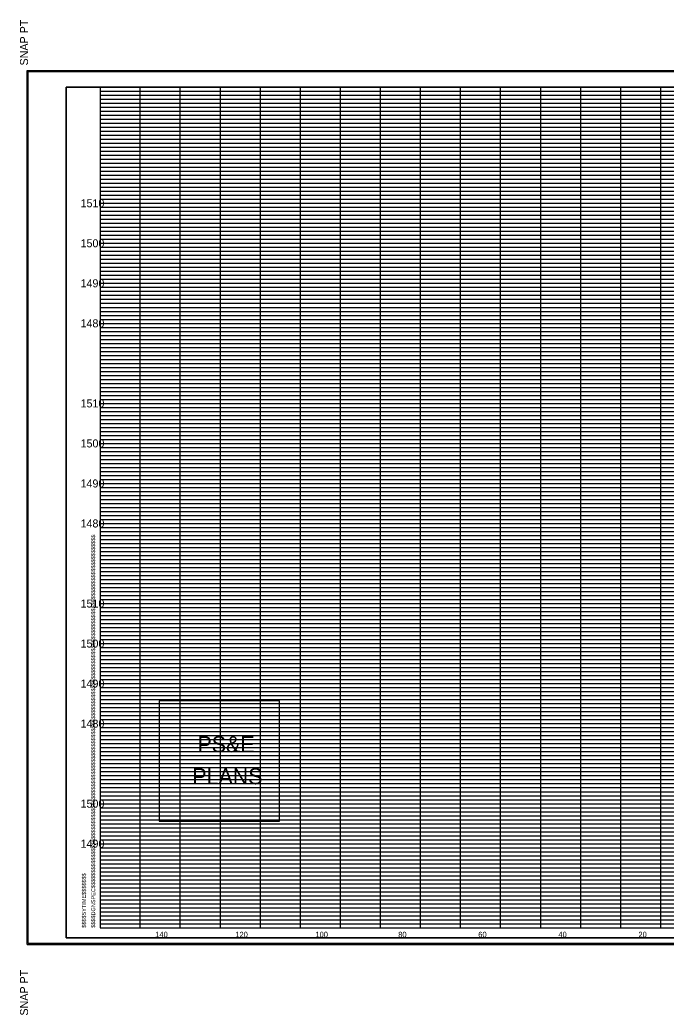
# Model space of a CAD drawing. Extents: x 980 to 1324, y 978 to 1497.
# Drawn here: x 979.9 to 1141.3, y 978.2 to 1226.8 of the extents above; entities that cross this region are included whole.
import ezdxf

# ---------------------------------------------------------------- set-up
doc = ezdxf.new("R2010")
doc.units = 0
for name, color, linetype in [('DESIGN - SHEET - Corner Text', 7, 'Continuous'), ('DESIGN - SHEET - Light Grid', 7, 'Continuous'), ('DESIGN - SHEET - Linework', 7, 'Continuous'), ('DESIGN - SHEET - Plot Shape', 7, 'Continuous'), ('DESIGN - TYPICAL - Text', 7, 'Continuous')]:
    doc.layers.add(name, color=color, linetype=linetype)

# ---------------------------------------------------------------- blocks, each defined once
blk = doc.blocks.new('XSTSHT')
at = {"layer": 'DESIGN - SHEET - Light Grid'}
for p, q in [((0, 20.9), (8, 20.9)), ((8, 20.9), (16, 20.9)), ((0, 20.8), (8, 20.8)), ((0, 20.7), (8, 20.7)), ((8, 20.8), (16, 20.8)), ((8, 20.7), (16, 20.7)), ((0, 20.6), (8, 20.6)), ((0, 20.5), (8, 20.5)), ((0, 20.4), (8, 20.4)), ((8, 20.6), (16, 20.6)), ((8, 20.5), (16, 20.5)), ((8, 20.4), (16, 20.4)), ((0, 20.3), (8, 20.3)), ((0, 20.2), (8, 20.2)), ((8, 20.3), (16, 20.3)), ((8, 20.2), (16, 20.2)), ((0, 20.1), (8, 20.1)), ((0, 19.9), (8, 19.9)), ((8, 20.1), (16, 20.1)), ((8, 19.9), (16, 19.9)), ((0, 19.8), (8, 19.8)), ((0, 19.7), (8, 19.7)), ((8, 19.8), (16, 19.8)), ((8, 19.7), (16, 19.7)), ((0, 19.6), (8, 19.6)), ((0, 19.5), (8, 19.5)), ((0, 19.4), (8, 19.4)), ((8, 19.6), (16, 19.6)), ((8, 19.5), (16, 19.5)), ((8, 19.4), (16, 19.4)), ((0, 19.3), (8, 19.3)), ((0, 19.2), (8, 19.2)), ((8, 19.3), (16, 19.3)), ((8, 19.2), (16, 19.2)), ((0, 19.1), (8, 19.1)), ((0, 18.9), (8, 18.9)), ((8, 19.1), (16, 19.1)), ((8, 18.9), (16, 18.9)), ((0, 18.8), (8, 18.8)), ((0, 18.7), (8, 18.7)), ((8, 18.8), (16, 18.8)), ((8, 18.7), (16, 18.7)), ((0, 18.6), (8, 18.6)), ((0, 18.5), (8, 18.5)), ((0, 18.4), (8, 18.4)), ((8, 18.6), (16, 18.6)), ((8, 18.5), (16, 18.5)), ((8, 18.4), (16, 18.4)), ((0, 18.3), (8, 18.3)), ((0, 18.2), (8, 18.2)), ((8, 18.3), (16, 18.3)), ((8, 18.2), (16, 18.2)), ((0, 18.1), (8, 18.1)), ((8, 18.1), (16, 18.1)), ((0, 17.9), (8, 17.9)), ((0, 17.8), (8, 17.8)), ((0, 17.7), (8, 17.7)), ((8, 17.9), (16, 17.9)), ((8, 17.8), (16, 17.8)), ((8, 17.7), (16, 17.7)), ((0, 17.6), (8, 17.6)), ((0, 17.5), (8, 17.5)), ((8, 17.6), (16, 17.6)), ((8, 17.5), (16, 17.5)), ((0, 17.4), (8, 17.4)), ((0, 17.3), (8, 17.3)), ((0, 17.2), (8, 17.2)), ((8, 17.4), (16, 17.4)), ((8, 17.3), (16, 17.3)), ((8, 17.2), (16, 17.2)), ((0, 17.1), (8, 17.1)), ((8, 17.1), (16, 17.1)), ((0, 16.9), (8, 16.9)), ((0, 16.8), (8, 16.8)), ((0, 16.7), (8, 16.7)), ((8, 16.9), (16, 16.9)), ((8, 16.8), (16, 16.8)), ((8, 16.7), (16, 16.7)), ((0, 16.6), (8, 16.6)), ((0, 16.5), (8, 16.5)), ((8, 16.6), (16, 16.6)), ((8, 16.5), (16, 16.5)), ((0, 16.4), (8, 16.4)), ((0, 16.3), (8, 16.3)), ((0, 16.2), (8, 16.2)), ((8, 16.4), (16, 16.4)), ((8, 16.3), (16, 16.3)), ((8, 16.2), (16, 16.2)), ((0, 16.1), (8, 16.1)), ((8, 16.1), (16, 16.1)), ((0, 15.9), (8, 15.9)), ((0, 15.8), (8, 15.8)), ((0, 15.7), (8, 15.7)), ((8, 15.9), (16, 15.9)), ((8, 15.8), (16, 15.8)), ((8, 15.7), (16, 15.7)), ((0, 15.6), (8, 15.6)), ((0, 15.5), (8, 15.5)), ((8, 15.6), (16, 15.6)), ((8, 15.5), (16, 15.5)), ((0, 15.4), (8, 15.4)), ((0, 15.3), (8, 15.3)), ((0, 15.2), (8, 15.2)), ((8, 15.4), (16, 15.4)), ((8, 15.3), (16, 15.3)), ((8, 15.2), (16, 15.2)), ((0, 15.1), (8, 15.1)), ((8, 15.1), (16, 15.1)), ((0, 14.9), (8, 14.9)), ((0, 14.8), (8, 14.8)), ((0, 14.7), (8, 14.7)), ((8, 14.9), (16, 14.9)), ((8, 14.8), (16, 14.8)), ((8, 14.7), (16, 14.7)), ((0, 14.6), (8, 14.6)), ((0, 14.5), (8, 14.5)), ((8, 14.6), (16, 14.6)), ((8, 14.5), (16, 14.5)), ((0, 14.4), (8, 14.4)), ((0, 14.3), (8, 14.3)), ((0, 14.2), (8, 14.2)), ((8, 14.4), (16, 14.4)), ((8, 14.3), (16, 14.3)), ((8, 14.2), (16, 14.2)), ((0, 14.1), (8, 14.1)), ((8, 14.1), (16, 14.1)), ((0, 13.9), (8, 13.9)), ((0, 13.8), (8, 13.8)), ((0, 13.7), (8, 13.7)), ((8, 13.9), (16, 13.9)), ((8, 13.8), (16, 13.8)), ((8, 13.7), (16, 13.7)), ((0, 13.6), (8, 13.6)), ((0, 13.5), (8, 13.5)), ((8, 13.6), (16, 13.6)), ((8, 13.5), (16, 13.5)), ((0, 13.4), (8, 13.4)), ((0, 13.3), (8, 13.3)), ((0, 13.2), (8, 13.2)), ((8, 13.4), (16, 13.4)), ((8, 13.3), (16, 13.3)), ((8, 13.2), (16, 13.2)), ((0, 13.1), (8, 13.1)), ((8, 13.1), (16, 13.1)), ((0, 12.9), (8, 12.9)), ((0, 12.8), (8, 12.8)), ((0, 12.7), (8, 12.7)), ((8, 12.9), (16, 12.9)), ((8, 12.8), (16, 12.8)), ((8, 12.7), (16, 12.7)), ((0, 12.6), (8, 12.6)), ((0, 12.5), (8, 12.5)), ((8, 12.6), (16, 12.6)), ((8, 12.5), (16, 12.5)), ((0, 12.4), (8, 12.4)), ((0, 12.3), (8, 12.3)), ((0, 12.2), (8, 12.2)), ((8, 12.4), (16, 12.4)), ((8, 12.3), (16, 12.3)), ((8, 12.2), (16, 12.2)), ((0, 12.1), (8, 12.1)), ((8, 12.1), (16, 12.1)), ((0, 11.9), (8, 11.9)), ((0, 11.8), (8, 11.8)), ((0, 11.7), (8, 11.7)), ((8, 11.9), (16, 11.9)), ((8, 11.8), (16, 11.8)), ((8, 11.7), (16, 11.7)), ((0, 11.6), (8, 11.6)), ((0, 11.5), (8, 11.5)), ((8, 11.6), (16, 11.6)), ((8, 11.5), (16, 11.5)), ((0, 11.4), (8, 11.4)), ((0, 11.3), (8, 11.3)), ((0, 11.2), (8, 11.2)), ((8, 11.4), (16, 11.4)), ((8, 11.3), (16, 11.3)), ((8, 11.2), (16, 11.2)), ((0, 11.1), (8, 11.1)), ((8, 11.1), (16, 11.1)), ((0, 10.9), (8, 10.9)), ((0, 10.8), (8, 10.8)), ((0, 10.7), (8, 10.7)), ((8, 10.9), (16, 10.9)), ((8, 10.8), (16, 10.8)), ((8, 10.7), (16, 10.7)), ((0, 10.6), (8, 10.6)), ((0, 10.5), (8, 10.5)), ((8, 10.6), (16, 10.6)), ((8, 10.5), (16, 10.5)), ((0, 10.4), (8, 10.4)), ((0, 10.3), (8, 10.3)), ((0, 10.2), (8, 10.2)), ((8, 10.4), (16, 10.4)), ((8, 10.3), (16, 10.3)), ((8, 10.2), (16, 10.2)), ((0, 10.1), (8, 10.1)), ((8, 10.1), (16, 10.1)), ((0, 9.9), (8, 9.9)), ((0, 9.8), (8, 9.8)), ((0, 9.7), (8, 9.7)), ((8, 9.9), (16, 9.9)), ((8, 9.8), (16, 9.8)), ((8, 9.7), (16, 9.7)), ((0, 9.6), (8, 9.6)), ((0, 9.5), (8, 9.5)), ((8, 9.6), (16, 9.6)), ((8, 9.5), (16, 9.5)), ((0, 9.4), (8, 9.4)), ((0, 9.3), (8, 9.3)), ((0, 9.2), (8, 9.2)), ((8, 9.4), (16, 9.4)), ((8, 9.3), (16, 9.3)), ((8, 9.2), (16, 9.2)), ((0, 9.1), (8, 9.1)), ((8, 9.1), (16, 9.1)), ((0, 8.9), (8, 8.9)), ((0, 8.8), (8, 8.8)), ((8, 8.9), (16, 8.9)), ((8, 8.8), (16, 8.8)), ((0, 8.7), (8, 8.7)), ((0, 8.6), (8, 8.6)), ((0, 8.5), (8, 8.5)), ((8, 8.7), (16, 8.7)), ((8, 8.6), (16, 8.6)), ((8, 8.5), (16, 8.5)), ((0, 8.4), (8, 8.4)), ((0, 8.3), (8, 8.3)), ((8, 8.4), (16, 8.4)), ((8, 8.3), (16, 8.3)), ((0, 8.2), (8, 8.2)), ((0, 8.1), (8, 8.1)), ((8, 8.2), (16, 8.2)), ((8, 8.1), (16, 8.1)), ((0, 7.9), (8, 7.9)), ((0, 7.8), (8, 7.8)), ((8, 7.9), (16, 7.9)), ((8, 7.8), (16, 7.8)), ((0, 7.7), (8, 7.7)), ((0, 7.6), (8, 7.6)), ((0, 7.5), (8, 7.5)), ((8, 7.7), (16, 7.7)), ((8, 7.6), (16, 7.6)), ((8, 7.5), (16, 7.5)), ((0, 7.4), (8, 7.4)), ((0, 7.3), (8, 7.3)), ((8, 7.4), (16, 7.4)), ((8, 7.3), (16, 7.3)), ((0, 7.2), (8, 7.2)), ((0, 7.1), (8, 7.1)), ((8, 7.2), (16, 7.2)), ((8, 7.1), (16, 7.1)), ((0, 6.9), (8, 6.9)), ((0, 6.8), (8, 6.8)), ((8, 6.9), (16, 6.9)), ((8, 6.8), (16, 6.8)), ((0, 6.7), (8, 6.7)), ((0, 6.6), (8, 6.6)), ((0, 6.5), (8, 6.5)), ((8, 6.7), (16, 6.7)), ((8, 6.6), (16, 6.6)), ((8, 6.5), (16, 6.5)), ((0, 6.4), (8, 6.4)), ((0, 6.3), (8, 6.3)), ((8, 6.4), (16, 6.4)), ((8, 6.3), (16, 6.3)), ((0, 6.2), (8, 6.2)), ((0, 6.1), (8, 6.1)), ((8, 6.2), (16, 6.2)), ((8, 6.1), (16, 6.1)), ((0, 5.9), (8, 5.9)), ((0, 5.8), (8, 5.8)), ((8, 5.9), (16, 5.9)), ((8, 5.8), (16, 5.8)), ((0, 5.7), (8, 5.7)), ((0, 5.6), (8, 5.6)), ((0, 5.5), (8, 5.5)), ((8, 5.7), (16, 5.7)), ((8, 5.6), (16, 5.6)), ((8, 5.5), (16, 5.5)), ((0, 5.4), (8, 5.4)), ((0, 5.3), (8, 5.3)), ((8, 5.4), (16, 5.4)), ((8, 5.3), (16, 5.3)), ((0, 5.2), (8, 5.2)), ((0, 5.1), (8, 5.1)), ((8, 5.2), (16, 5.2)), ((8, 5.1), (16, 5.1)), ((0, 4.9), (8, 4.9)), ((0, 4.8), (8, 4.8)), ((8, 4.9), (16, 4.9)), ((8, 4.8), (16, 4.8)), ((0, 4.7), (8, 4.7)), ((0, 4.6), (8, 4.6)), ((0, 4.5), (8, 4.5)), ((8, 4.7), (16, 4.7)), ((8, 4.6), (16, 4.6)), ((8, 4.5), (16, 4.5)), ((0, 4.4), (8, 4.4)), ((0, 4.3), (8, 4.3)), ((8, 4.4), (16, 4.4)), ((8, 4.3), (16, 4.3)), ((0, 4.2), (8, 4.2)), ((0, 4.1), (8, 4.1)), ((8, 4.2), (16, 4.2)), ((8, 4.1), (16, 4.1)), ((0, 3.9), (8, 3.9)), ((0, 3.8), (8, 3.8)), ((8, 3.9), (16, 3.9)), ((8, 3.8), (16, 3.8)), ((0, 3.7), (8, 3.7)), ((0, 3.6), (8, 3.6)), ((0, 3.5), (8, 3.5)), ((8, 3.7), (16, 3.7)), ((8, 3.6), (16, 3.6)), ((8, 3.5), (16, 3.5)), ((0, 3.4), (8, 3.4)), ((0, 3.3), (8, 3.3)), ((8, 3.4), (16, 3.4)), ((8, 3.3), (16, 3.3)), ((0, 3.2), (8, 3.2)), ((0, 3.1), (8, 3.1)), ((8, 3.2), (16, 3.2)), ((8, 3.1), (16, 3.1)), ((0, 2.9), (8, 2.9)), ((0, 2.8), (8, 2.8)), ((8, 2.9), (16, 2.9)), ((8, 2.8), (16, 2.8)), ((0, 2.7), (8, 2.7)), ((0, 2.6), (8, 2.6)), ((0, 2.5), (8, 2.5)), ((8, 2.7), (16, 2.7)), ((8, 2.6), (16, 2.6)), ((8, 2.5), (16, 2.5)), ((0, 2.4), (8, 2.4)), ((0, 2.3), (8, 2.3)), ((8, 2.4), (16, 2.4)), ((8, 2.3), (16, 2.3)), ((0, 2.2), (8, 2.2)), ((0, 2.1), (8, 2.1)), ((8, 2.2), (16, 2.2)), ((8, 2.1), (16, 2.1)), ((0, 1.9), (8, 1.9)), ((0, 1.8), (8, 1.8)), ((8, 1.9), (16, 1.9)), ((8, 1.8), (16, 1.8)), ((0, 1.7), (8, 1.7)), ((0, 1.6), (8, 1.6)), ((0, 1.5), (8, 1.5)), ((8, 1.7), (16, 1.7)), ((8, 1.6), (16, 1.6)), ((8, 1.5), (16, 1.5)), ((0, 1.4), (8, 1.4)), ((0, 1.3), (8, 1.3)), ((8, 1.4), (16, 1.4)), ((8, 1.3), (16, 1.3)), ((0, 1.2), (8, 1.2)), ((0, 1.1), (8, 1.1)), ((8, 1.2), (16, 1.2)), ((8, 1.1), (16, 1.1)), ((0, 0.9), (8, 0.9)), ((0, 0.8), (8, 0.8)), ((8, 0.9), (16, 0.9)), ((8, 0.8), (16, 0.8)), ((0, 0.7), (8, 0.7)), ((0, 0.6), (8, 0.6)), ((0, 0.5), (8, 0.5)), ((8, 0.7), (16, 0.7)), ((8, 0.6), (16, 0.6)), ((8, 0.5), (16, 0.5)), ((0, 0.4), (8, 0.4)), ((0, 0.3), (8, 0.3)), ((8, 0.4), (16, 0.4)), ((8, 0.3), (16, 0.3)), ((0, 0.2), (8, 0.2)), ((0, 0.1), (8, 0.1)), ((8, 0.2), (16, 0.2)), ((8, 0.1), (16, 0.1))]:
    blk.add_line(p, q, dxfattribs=at)
at = {"layer": 'DESIGN - SHEET - Linework'}
for p, q in [((-1.823, -0.414), (-1.823, 21.414)), ((-1.823, 21.414), (32.217, 21.414)), ((1, 0), (1, 21)), ((2, 0), (2, 21)), ((3, 0), (3, 21)), ((4, 0), (4, 21)), ((5, 0), (5, 21)), ((6, 0), (6, 21)), ((7, 0), (7, 21)), ((8, 0), (8, 21)), ((9, 0), (9, 21)), ((10, 0), (10, 21)), ((11, 0), (11, 21)), ((12, 0), (12, 21)), ((13, 0), (13, 21)), ((14, 0), (14, 21)), ((0, 20), (28, 20)), ((0, 19), (32, 19)), ((0, 18), (32, 18)), ((0, 17), (32, 17)), ((0, 16), (32, 16)), ((0, 15), (32, 15)), ((0, 14), (32, 14)), ((0, 13), (32, 13)), ((0, 12), (32, 12)), ((0, 11), (32, 11)), ((0, 10), (32, 10)), ((0, 9), (32, 9)), ((0, 8), (32, 8)), ((0, 7), (32, 7)), ((0, 6), (32, 6)), ((0, 5), (32, 5)), ((0, 4), (32, 4)), ((0, 3), (32, 3)), ((0, 2), (32, 2)), ((0, 1), (32, 1)), ((-1.823, -0.414), (32.217, -0.414))]:
    blk.add_line(p, q, dxfattribs=at)
blk.add_lwpolyline([(0, 21), (0, 0), (32, 0), (32, 21), (0, 21)], dxfattribs=at)
at = {"layer": 'DESIGN - SHEET - Plot Shape'}
for points in [[(-1.803, 21.394), (32.197, 21.394), (32.197, -0.394), (-1.803, -0.394)], [(-0.85, 21), (32, 21), (32, -0.25), (-0.85, -0.25)]]:
    blk.add_lwpolyline(points, close=True, dxfattribs=at)
at = {"layer": 'DESIGN - SHEET - Corner Text'}
for s, height, p in [('  SNAP PT', 0.2, (-1.803, 21.394)), ('$$$$DGNSPEC$$$$$$$$$$$$$$$$$$$$$$$$$$$$$$$$$$$$$$$$$$$$$$$$$$$$$$$$$$$$$$$$$$$$$$$$$$$$$$$$$$$$$$$$$$$$$$$$$$$$$$$$$$$$$$$$$$$', 0.100002, (-0.126, 0)), ('$$$$SYTIME$$$$$$$', 0.1, (-0.358, 0)), ('SNAP PT  ', 0.2, (-1.803, -2.194))]:
    blk.add_text(s, height=height, rotation=90, dxfattribs=at).set_placement(p)

msp = doc.modelspace()

# ---------------------------------------------------------------- linework, layer by layer
at = {"layer": 'DESIGN - SHEET - Corner Text'}
msp.add_lwpolyline([(1014.76, 1056.66), (1014.76, 1026.66), (1044.76, 1026.66), (1044.76, 1056.66)], close=True, dxfattribs=at)
at = {"layer": 'DESIGN - SHEET - Plot Shape'}
msp.add_lwpolyline([(991.5, 997.5), (1320, 997.5), (1320, 1210), (991.5, 1210)], close=True, dxfattribs=at)

# ---------------------------------------------------------------- block references
at = {"layer": 'DESIGN - TYPICAL - Text', "xscale": 10, "yscale": 10}
msp.add_blockref('XSTSHT', (1000, 1000), dxfattribs=at)

# ---------------------------------------------------------------- texts
at = {"layer": 'DESIGN - SHEET - Corner Text'}
for s, p in [('PS&E', (1024.28, 1043.84)), ('PLANS', (1022.99, 1035.84))]:
    msp.add_text(s, height=4, dxfattribs=at).set_placement(p)
at = {"layer": 'DESIGN - TYPICAL - Text'}
for s, height, p in [('     1510     ', 2, (991.37, 1180)), ('     1500     ', 2, (991.37, 1170)), ('     1490     ', 2, (991.37, 1160)), ('     1480     ', 2, (991.37, 1150)), ('     1510     ', 2, (991.37, 1130)), ('     1500     ', 2, (991.37, 1120)), ('     1490     ', 2, (991.37, 1110)), ('     1480     ', 2, (991.37, 1100)), ('     1510     ', 2, (991.37, 1080)), ('     1500     ', 2, (991.37, 1070)), ('     1490     ', 2, (991.37, 1060)), ('     1480     ', 2, (991.37, 1050)), ('     1500     ', 2, (991.37, 1030)), ('     1490     ', 2, (991.37, 1020)), ('     140     ', 1.4, (1011.14, 997.6)), ('     120     ', 1.4, (1031.14, 997.6)), ('     100     ', 1.4, (1051.14, 997.6)), ('     80     ', 1.4, (1071.82, 997.6)), ('     60     ', 1.4, (1091.82, 997.6)), ('     40     ', 1.4, (1111.82, 997.6)), ('     20     ', 1.4, (1131.82, 997.6))]:
    msp.add_text(s, height=height, dxfattribs=at).set_placement(p)

doc.saveas('drawing.dxf')
